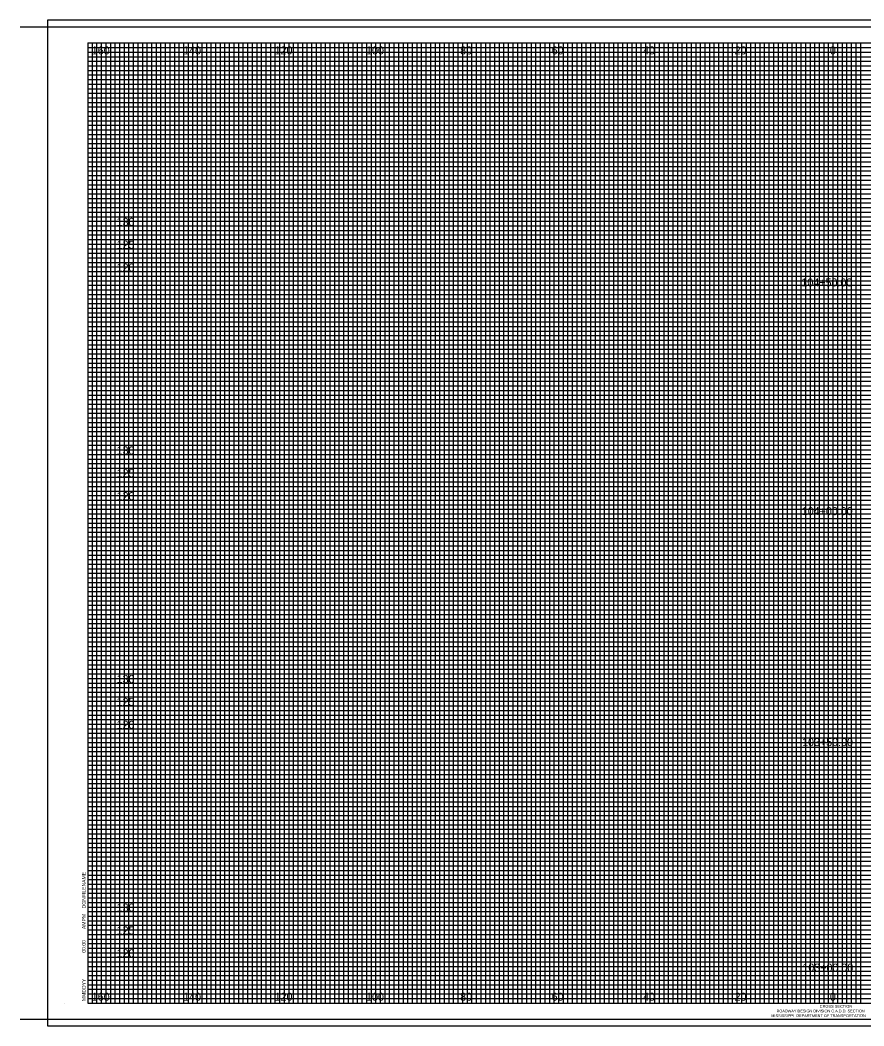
# Model space of a CAD drawing. Extents: x -3604 to 2303, y -13 to 9543.
# Drawn here: x -3604.5 to -3420, y 6914.1 to 7134.1 of the extents above; entities that cross this region are included whole.
import ezdxf

# ---------------------------------------------------------------- set-up
doc = ezdxf.new("R2010")
doc.units = 0
for name, color, linetype in [('SHEET_BORDER', 7, 'Continuous'), ('SHEET_BORDER_TX', 7, 'Continuous'), ('SHEET_DATE_DGN_TX', 7, 'Continuous'), ('SHEET_PLOTTING_SHAPE', 7, 'Continuous'), ('XS_SHEET_LABELS_ELEVATION', 7, 'Continuous'), ('XS_SHEET_LABELS_OFFSET', 7, 'Continuous'), ('XS_SHEET_LABELS_STATION', 7, 'Continuous'), ('XS_SHEET_MAJOR_GRIDS', 7, 'Continuous'), ('XS_SHEET_MEDIUM_GRIDS', 7, 'Continuous'), ('XS_SHEET_MINOR_GRIDS', 7, 'Continuous')]:
    doc.layers.add(name, color=color, linetype=linetype)

msp = doc.modelspace()

# ---------------------------------------------------------------- linework, layer by layer
at = {"layer": 'SHEET_BORDER'}
for p, q in [((-3604.48, 7132.59), (-3252.48, 7132.59)), ((-3589.68, 7129.09), (-3254.68, 7129.09)), ((-3589.68, 7129.09), (-3589.68, 6919.09)), ((-3445.68, 6919.09), (-3445.68, 7129.09)), ((-3594.68, 6919.09), (-3594.68, 6919.09)), ((-3589.68, 6919.09), (-3254.68, 6919.09)), ((-3604.48, 6915.59), (-3252.48, 6915.59))]:
    msp.add_line(p, q, dxfattribs=at)
at = {"layer": 'SHEET_PLOTTING_SHAPE'}
msp.add_lwpolyline([(-3598.48, 6914.09), (-3252.48, 6914.09), (-3252.48, 7134.09), (-3598.48, 7134.09)], close=True, dxfattribs=at)
at = {"layer": 'XS_SHEET_MAJOR_GRIDS'}
for p, q in [((-3584.68, 6919.09), (-3584.68, 7129.09)), ((-3574.68, 6919.09), (-3574.68, 7129.09)), ((-3564.68, 6919.09), (-3564.68, 7129.09)), ((-3554.68, 6919.09), (-3554.68, 7129.09)), ((-3544.68, 6919.09), (-3544.68, 7129.09)), ((-3534.68, 6919.09), (-3534.68, 7129.09)), ((-3524.68, 6919.09), (-3524.68, 7129.09)), ((-3514.68, 6919.09), (-3514.68, 7129.09)), ((-3504.68, 6919.09), (-3504.68, 7129.09)), ((-3494.68, 6919.09), (-3494.68, 7129.09)), ((-3484.68, 6919.09), (-3484.68, 7129.09)), ((-3474.68, 6919.09), (-3474.68, 7129.09)), ((-3464.68, 6919.09), (-3464.68, 7129.09)), ((-3454.68, 6919.09), (-3454.68, 7129.09)), ((-3444.68, 6919.09), (-3444.68, 7129.09)), ((-3434.68, 6919.09), (-3434.68, 7129.09)), ((-3424.68, 6919.09), (-3424.68, 7129.09)), ((-3589.68, 7119.09), (-3254.68, 7119.09)), ((-3589.68, 7109.09), (-3254.68, 7109.09)), ((-3589.68, 7099.09), (-3254.68, 7099.09)), ((-3589.68, 7089.09), (-3254.68, 7089.09)), ((-3589.68, 7079.09), (-3254.68, 7079.09)), ((-3589.68, 7069.09), (-3254.68, 7069.09)), ((-3589.68, 7059.09), (-3254.68, 7059.09)), ((-3589.68, 7049.09), (-3254.68, 7049.09)), ((-3589.68, 7039.09), (-3254.68, 7039.09)), ((-3589.68, 7029.09), (-3254.68, 7029.09)), ((-3589.68, 7019.09), (-3254.68, 7019.09)), ((-3589.68, 7009.09), (-3254.68, 7009.09)), ((-3589.68, 6999.09), (-3254.68, 6999.09)), ((-3589.68, 6989.09), (-3254.68, 6989.09)), ((-3589.68, 6979.09), (-3254.68, 6979.09)), ((-3589.68, 6969.09), (-3254.68, 6969.09)), ((-3589.68, 6959.09), (-3254.68, 6959.09)), ((-3589.68, 6949.09), (-3254.68, 6949.09)), ((-3589.68, 6939.09), (-3254.68, 6939.09)), ((-3589.68, 6929.09), (-3254.68, 6929.09))]:
    msp.add_line(p, q, dxfattribs=at)
at = {"layer": 'XS_SHEET_MEDIUM_GRIDS'}
for p, q in [((-3579.68, 6919.09), (-3579.68, 7129.09)), ((-3569.68, 6919.09), (-3569.68, 7129.09)), ((-3559.68, 6919.09), (-3559.68, 7129.09)), ((-3549.68, 6919.09), (-3549.68, 7129.09)), ((-3539.68, 6919.09), (-3539.68, 7129.09)), ((-3529.68, 6919.09), (-3529.68, 7129.09)), ((-3519.68, 6919.09), (-3519.68, 7129.09)), ((-3509.68, 6919.09), (-3509.68, 7129.09)), ((-3499.68, 6919.09), (-3499.68, 7129.09)), ((-3489.68, 6919.09), (-3489.68, 7129.09)), ((-3479.68, 6919.09), (-3479.68, 7129.09)), ((-3469.68, 6919.09), (-3469.68, 7129.09)), ((-3459.68, 6919.09), (-3459.68, 7129.09)), ((-3449.68, 6919.09), (-3449.68, 7129.09)), ((-3439.68, 6919.09), (-3439.68, 7129.09)), ((-3429.68, 6919.09), (-3429.68, 7129.09)), ((-3589.68, 7124.09), (-3281.68, 7124.09)), ((-3589.68, 7114.09), (-3254.68, 7114.09)), ((-3589.68, 7104.09), (-3254.68, 7104.09)), ((-3589.68, 7094.09), (-3254.68, 7094.09)), ((-3589.68, 7084.09), (-3254.68, 7084.09)), ((-3589.68, 7074.09), (-3254.68, 7074.09)), ((-3589.68, 7064.09), (-3254.68, 7064.09)), ((-3589.68, 7054.09), (-3254.68, 7054.09)), ((-3589.68, 7044.09), (-3254.68, 7044.09)), ((-3589.68, 7034.09), (-3254.68, 7034.09)), ((-3589.68, 7024.09), (-3254.68, 7024.09)), ((-3589.68, 7014.09), (-3254.68, 7014.09)), ((-3589.68, 7004.09), (-3254.68, 7004.09)), ((-3589.68, 6994.09), (-3254.68, 6994.09)), ((-3589.68, 6984.09), (-3254.68, 6984.09)), ((-3589.68, 6974.09), (-3254.68, 6974.09)), ((-3589.68, 6964.09), (-3254.68, 6964.09)), ((-3589.68, 6954.09), (-3254.68, 6954.09)), ((-3589.68, 6944.09), (-3254.68, 6944.09)), ((-3589.68, 6934.09), (-3254.68, 6934.09)), ((-3589.68, 6924.09), (-3264.68, 6924.09))]:
    msp.add_line(p, q, dxfattribs=at)
at = {"layer": 'XS_SHEET_MINOR_GRIDS'}
for p, q in [((-3589.68, 7128.09), (-3281.68, 7128.09)), ((-3588.68, 6919.09), (-3588.68, 7129.09)), ((-3587.68, 6919.09), (-3587.68, 7129.09)), ((-3586.68, 6919.09), (-3586.68, 7129.09)), ((-3585.68, 6919.09), (-3585.68, 7129.09)), ((-3583.68, 6919.09), (-3583.68, 7129.09)), ((-3582.68, 6919.09), (-3582.68, 7129.09)), ((-3581.68, 6919.09), (-3581.68, 7129.09)), ((-3580.68, 6919.09), (-3580.68, 7129.09)), ((-3578.68, 6919.09), (-3578.68, 7129.09)), ((-3577.68, 6919.09), (-3577.68, 7129.09)), ((-3576.68, 6919.09), (-3576.68, 7129.09)), ((-3575.68, 6919.09), (-3575.68, 7129.09)), ((-3573.68, 6919.09), (-3573.68, 7129.09)), ((-3572.68, 6919.09), (-3572.68, 7129.09)), ((-3571.68, 6919.09), (-3571.68, 7129.09)), ((-3570.68, 6919.09), (-3570.68, 7129.09)), ((-3568.68, 6919.09), (-3568.68, 7129.09)), ((-3567.68, 6919.09), (-3567.68, 7129.09)), ((-3566.68, 6919.09), (-3566.68, 7129.09)), ((-3565.68, 6919.09), (-3565.68, 7129.09)), ((-3563.68, 6919.09), (-3563.68, 7129.09)), ((-3562.68, 6919.09), (-3562.68, 7129.09)), ((-3561.68, 6919.09), (-3561.68, 7129.09)), ((-3560.68, 6919.09), (-3560.68, 7129.09)), ((-3558.68, 6919.09), (-3558.68, 7129.09)), ((-3557.68, 6919.09), (-3557.68, 7129.09)), ((-3556.68, 6919.09), (-3556.68, 7129.09)), ((-3555.68, 6919.09), (-3555.68, 7129.09)), ((-3553.68, 6919.09), (-3553.68, 7129.09)), ((-3552.68, 6919.09), (-3552.68, 7129.09)), ((-3551.68, 6919.09), (-3551.68, 7129.09)), ((-3550.68, 6919.09), (-3550.68, 7129.09)), ((-3548.68, 6919.09), (-3548.68, 7129.09)), ((-3547.68, 6919.09), (-3547.68, 7129.09)), ((-3546.68, 6919.09), (-3546.68, 7129.09)), ((-3545.68, 6919.09), (-3545.68, 7129.09)), ((-3543.68, 6919.09), (-3543.68, 7129.09)), ((-3542.68, 6919.09), (-3542.68, 7129.09)), ((-3541.68, 6919.09), (-3541.68, 7129.09)), ((-3540.68, 6919.09), (-3540.68, 7129.09)), ((-3538.68, 6919.09), (-3538.68, 7129.09)), ((-3537.68, 6919.09), (-3537.68, 7129.09)), ((-3536.68, 6919.09), (-3536.68, 7129.09)), ((-3535.68, 6919.09), (-3535.68, 7129.09)), ((-3533.68, 6919.09), (-3533.68, 7129.09)), ((-3532.68, 6919.09), (-3532.68, 7129.09)), ((-3531.68, 6919.09), (-3531.68, 7129.09)), ((-3530.68, 6919.09), (-3530.68, 7129.09)), ((-3528.68, 6919.09), (-3528.68, 7129.09)), ((-3527.68, 6919.09), (-3527.68, 7129.09)), ((-3526.68, 6919.09), (-3526.68, 7129.09)), ((-3525.68, 6919.09), (-3525.68, 7129.09)), ((-3523.68, 6919.09), (-3523.68, 7129.09)), ((-3522.68, 6919.09), (-3522.68, 7129.09)), ((-3521.68, 6919.09), (-3521.68, 7129.09)), ((-3520.68, 6919.09), (-3520.68, 7129.09)), ((-3518.68, 6919.09), (-3518.68, 7129.09)), ((-3517.68, 6919.09), (-3517.68, 7129.09)), ((-3516.68, 6919.09), (-3516.68, 7129.09)), ((-3515.68, 6919.09), (-3515.68, 7129.09)), ((-3513.68, 6919.09), (-3513.68, 7129.09)), ((-3512.68, 6919.09), (-3512.68, 7129.09)), ((-3511.68, 6919.09), (-3511.68, 7129.09)), ((-3510.68, 6919.09), (-3510.68, 7129.09)), ((-3508.68, 6919.09), (-3508.68, 7129.09)), ((-3507.68, 6919.09), (-3507.68, 7129.09)), ((-3506.68, 6919.09), (-3506.68, 7129.09)), ((-3505.68, 6919.09), (-3505.68, 7129.09)), ((-3503.68, 6919.09), (-3503.68, 7129.09)), ((-3502.68, 6919.09), (-3502.68, 7129.09)), ((-3501.68, 6919.09), (-3501.68, 7129.09)), ((-3500.68, 6919.09), (-3500.68, 7129.09)), ((-3498.68, 6919.09), (-3498.68, 7129.09)), ((-3497.68, 6919.09), (-3497.68, 7129.09)), ((-3496.68, 6919.09), (-3496.68, 7129.09)), ((-3495.68, 6919.09), (-3495.68, 7129.09)), ((-3493.68, 6919.09), (-3493.68, 7129.09)), ((-3492.68, 6919.09), (-3492.68, 7129.09)), ((-3491.68, 6919.09), (-3491.68, 7129.09)), ((-3490.68, 6919.09), (-3490.68, 7129.09)), ((-3488.68, 6919.09), (-3488.68, 7129.09)), ((-3487.68, 6919.09), (-3487.68, 7129.09)), ((-3486.68, 6919.09), (-3486.68, 7129.09)), ((-3485.68, 6919.09), (-3485.68, 7129.09)), ((-3483.68, 6919.09), (-3483.68, 7129.09)), ((-3482.68, 6919.09), (-3482.68, 7129.09)), ((-3481.68, 6919.09), (-3481.68, 7129.09)), ((-3480.68, 6919.09), (-3480.68, 7129.09)), ((-3478.68, 6919.09), (-3478.68, 7129.09)), ((-3477.68, 6919.09), (-3477.68, 7129.09)), ((-3476.68, 6919.09), (-3476.68, 7129.09)), ((-3475.68, 6919.09), (-3475.68, 7129.09)), ((-3473.68, 6919.09), (-3473.68, 7129.09)), ((-3472.68, 6919.09), (-3472.68, 7129.09)), ((-3471.68, 6919.09), (-3471.68, 7129.09)), ((-3470.68, 6919.09), (-3470.68, 7129.09)), ((-3468.68, 6919.09), (-3468.68, 7129.09)), ((-3467.68, 6919.09), (-3467.68, 7129.09)), ((-3466.68, 6919.09), (-3466.68, 7129.09)), ((-3465.68, 6919.09), (-3465.68, 7129.09)), ((-3463.68, 6919.09), (-3463.68, 7129.09)), ((-3462.68, 6919.09), (-3462.68, 7129.09)), ((-3461.68, 6919.09), (-3461.68, 7129.09)), ((-3460.68, 6919.09), (-3460.68, 7129.09)), ((-3458.68, 6919.09), (-3458.68, 7129.09)), ((-3457.68, 6919.09), (-3457.68, 7129.09)), ((-3456.68, 6919.09), (-3456.68, 7129.09)), ((-3455.68, 6919.09), (-3455.68, 7129.09)), ((-3453.68, 6919.09), (-3453.68, 7129.09)), ((-3452.68, 6919.09), (-3452.68, 7129.09)), ((-3451.68, 6919.09), (-3451.68, 7129.09)), ((-3450.68, 6919.09), (-3450.68, 7129.09)), ((-3448.68, 6919.09), (-3448.68, 7129.09)), ((-3447.68, 6919.09), (-3447.68, 7129.09)), ((-3446.68, 6919.09), (-3446.68, 7129.09)), ((-3443.68, 6919.09), (-3443.68, 7129.09)), ((-3442.68, 6919.09), (-3442.68, 7129.09)), ((-3441.68, 6919.09), (-3441.68, 7129.09)), ((-3440.68, 6919.09), (-3440.68, 7129.09)), ((-3438.68, 6919.09), (-3438.68, 7129.09)), ((-3437.68, 6919.09), (-3437.68, 7129.09)), ((-3436.68, 6919.09), (-3436.68, 7129.09)), ((-3435.68, 6919.09), (-3435.68, 7129.09)), ((-3433.68, 6919.09), (-3433.68, 7129.09)), ((-3432.68, 6919.09), (-3432.68, 7129.09)), ((-3431.68, 6919.09), (-3431.68, 7129.09)), ((-3430.68, 6919.09), (-3430.68, 7129.09)), ((-3428.68, 6919.09), (-3428.68, 7129.09)), ((-3427.68, 6919.09), (-3427.68, 7129.09)), ((-3426.68, 6919.09), (-3426.68, 7129.09)), ((-3425.68, 6919.09), (-3425.68, 7129.09)), ((-3423.68, 6919.09), (-3423.68, 7129.09)), ((-3422.68, 6919.09), (-3422.68, 7129.09)), ((-3421.68, 6919.09), (-3421.68, 7129.09)), ((-3420.68, 6919.09), (-3420.68, 7129.09)), ((-3589.68, 7127.09), (-3281.68, 7127.09)), ((-3589.68, 7126.09), (-3281.68, 7126.09)), ((-3589.68, 7125.09), (-3281.68, 7125.09)), ((-3589.68, 7123.09), (-3281.68, 7123.09)), ((-3589.68, 7122.09), (-3281.68, 7122.09)), ((-3589.68, 7121.09), (-3281.68, 7121.09)), ((-3589.68, 7120.09), (-3254.68, 7120.09)), ((-3589.68, 7118.09), (-3254.68, 7118.09)), ((-3589.68, 7117.09), (-3254.68, 7117.09)), ((-3589.68, 7116.09), (-3254.68, 7116.09)), ((-3589.68, 7115.09), (-3254.68, 7115.09)), ((-3589.68, 7113.09), (-3254.68, 7113.09)), ((-3589.68, 7112.09), (-3254.68, 7112.09)), ((-3589.68, 7111.09), (-3254.68, 7111.09)), ((-3589.68, 7110.09), (-3254.68, 7110.09)), ((-3589.68, 7108.09), (-3254.68, 7108.09)), ((-3589.68, 7107.09), (-3254.68, 7107.09)), ((-3589.68, 7106.09), (-3254.68, 7106.09)), ((-3589.68, 7105.09), (-3254.68, 7105.09)), ((-3589.68, 7103.09), (-3254.68, 7103.09)), ((-3589.68, 7102.09), (-3254.68, 7102.09)), ((-3589.68, 7101.09), (-3254.68, 7101.09)), ((-3589.68, 7100.09), (-3254.68, 7100.09)), ((-3589.68, 7098.09), (-3254.68, 7098.09)), ((-3589.68, 7097.09), (-3254.68, 7097.09)), ((-3589.68, 7096.09), (-3254.68, 7096.09)), ((-3589.68, 7095.09), (-3254.68, 7095.09)), ((-3589.68, 7093.09), (-3254.68, 7093.09)), ((-3589.68, 7092.09), (-3254.68, 7092.09)), ((-3589.68, 7091.09), (-3254.68, 7091.09)), ((-3589.68, 7090.09), (-3254.68, 7090.09)), ((-3589.68, 7088.09), (-3254.68, 7088.09)), ((-3589.68, 7087.09), (-3254.68, 7087.09)), ((-3589.68, 7086.09), (-3254.68, 7086.09)), ((-3589.68, 7085.09), (-3254.68, 7085.09)), ((-3589.68, 7083.09), (-3254.68, 7083.09)), ((-3589.68, 7082.09), (-3254.68, 7082.09)), ((-3589.68, 7081.09), (-3254.68, 7081.09)), ((-3589.68, 7080.09), (-3254.68, 7080.09)), ((-3589.68, 7078.09), (-3254.68, 7078.09)), ((-3589.68, 7077.09), (-3254.68, 7077.09)), ((-3589.68, 7076.09), (-3254.68, 7076.09)), ((-3589.68, 7075.09), (-3254.68, 7075.09)), ((-3589.68, 7073.09), (-3254.68, 7073.09)), ((-3589.68, 7072.09), (-3254.68, 7072.09)), ((-3589.68, 7071.09), (-3254.68, 7071.09)), ((-3589.68, 7070.09), (-3254.68, 7070.09)), ((-3589.68, 7068.09), (-3254.68, 7068.09)), ((-3589.68, 7067.09), (-3254.68, 7067.09)), ((-3589.68, 7066.09), (-3254.68, 7066.09)), ((-3589.68, 7065.09), (-3254.68, 7065.09)), ((-3589.68, 7063.09), (-3254.68, 7063.09)), ((-3589.68, 7062.09), (-3254.68, 7062.09)), ((-3589.68, 7061.09), (-3254.68, 7061.09)), ((-3589.68, 7060.09), (-3254.68, 7060.09)), ((-3589.68, 7058.09), (-3254.68, 7058.09)), ((-3589.68, 7057.09), (-3254.68, 7057.09)), ((-3589.68, 7056.09), (-3254.68, 7056.09)), ((-3589.68, 7055.09), (-3254.68, 7055.09)), ((-3589.68, 7053.09), (-3254.68, 7053.09)), ((-3589.68, 7052.09), (-3254.68, 7052.09)), ((-3589.68, 7051.09), (-3254.68, 7051.09)), ((-3589.68, 7050.09), (-3254.68, 7050.09)), ((-3589.68, 7048.09), (-3254.68, 7048.09)), ((-3589.68, 7047.09), (-3254.68, 7047.09)), ((-3589.68, 7046.09), (-3254.68, 7046.09)), ((-3589.68, 7045.09), (-3254.68, 7045.09)), ((-3589.68, 7043.09), (-3254.68, 7043.09)), ((-3589.68, 7042.09), (-3254.68, 7042.09)), ((-3589.68, 7041.09), (-3254.68, 7041.09)), ((-3589.68, 7040.09), (-3254.68, 7040.09)), ((-3589.68, 7038.09), (-3254.68, 7038.09)), ((-3589.68, 7037.09), (-3254.68, 7037.09)), ((-3589.68, 7036.09), (-3254.68, 7036.09)), ((-3589.68, 7035.09), (-3254.68, 7035.09)), ((-3589.68, 7033.09), (-3254.68, 7033.09)), ((-3589.68, 7032.09), (-3254.68, 7032.09)), ((-3589.68, 7031.09), (-3254.68, 7031.09)), ((-3589.68, 7030.09), (-3254.68, 7030.09)), ((-3589.68, 7028.09), (-3254.68, 7028.09)), ((-3589.68, 7027.09), (-3254.68, 7027.09)), ((-3589.68, 7026.09), (-3254.68, 7026.09)), ((-3589.68, 7025.09), (-3254.68, 7025.09)), ((-3589.68, 7023.09), (-3254.68, 7023.09)), ((-3589.68, 7022.09), (-3254.68, 7022.09)), ((-3589.68, 7021.09), (-3254.68, 7021.09)), ((-3589.68, 7020.09), (-3254.68, 7020.09)), ((-3589.68, 7018.09), (-3254.68, 7018.09)), ((-3589.68, 7017.09), (-3254.68, 7017.09)), ((-3589.68, 7016.09), (-3254.68, 7016.09)), ((-3589.68, 7015.09), (-3254.68, 7015.09)), ((-3589.68, 7013.09), (-3254.68, 7013.09)), ((-3589.68, 7012.09), (-3254.68, 7012.09)), ((-3589.68, 7011.09), (-3254.68, 7011.09)), ((-3589.68, 7010.09), (-3254.68, 7010.09)), ((-3589.68, 7008.09), (-3254.68, 7008.09)), ((-3589.68, 7007.09), (-3254.68, 7007.09)), ((-3589.68, 7006.09), (-3254.68, 7006.09)), ((-3589.68, 7005.09), (-3254.68, 7005.09)), ((-3589.68, 7003.09), (-3254.68, 7003.09)), ((-3589.68, 7002.09), (-3254.68, 7002.09)), ((-3589.68, 7001.09), (-3254.68, 7001.09)), ((-3589.68, 7000.09), (-3254.68, 7000.09)), ((-3589.68, 6998.09), (-3254.68, 6998.09)), ((-3589.68, 6997.09), (-3254.68, 6997.09)), ((-3589.68, 6996.09), (-3254.68, 6996.09)), ((-3589.68, 6995.09), (-3254.68, 6995.09)), ((-3589.68, 6993.09), (-3254.68, 6993.09)), ((-3589.68, 6992.09), (-3254.68, 6992.09)), ((-3589.68, 6991.09), (-3254.68, 6991.09)), ((-3589.68, 6990.09), (-3254.68, 6990.09)), ((-3589.68, 6988.09), (-3254.68, 6988.09)), ((-3589.68, 6987.09), (-3254.68, 6987.09)), ((-3589.68, 6986.09), (-3254.68, 6986.09)), ((-3589.68, 6985.09), (-3254.68, 6985.09)), ((-3589.68, 6983.09), (-3254.68, 6983.09)), ((-3589.68, 6982.09), (-3254.68, 6982.09)), ((-3589.68, 6981.09), (-3254.68, 6981.09)), ((-3589.68, 6980.09), (-3254.68, 6980.09)), ((-3589.68, 6978.09), (-3254.68, 6978.09)), ((-3589.68, 6977.09), (-3254.68, 6977.09)), ((-3589.68, 6976.09), (-3254.68, 6976.09)), ((-3589.68, 6975.09), (-3254.68, 6975.09)), ((-3589.68, 6973.09), (-3254.68, 6973.09)), ((-3589.68, 6972.09), (-3254.68, 6972.09)), ((-3589.68, 6971.09), (-3254.68, 6971.09)), ((-3589.68, 6970.09), (-3254.68, 6970.09)), ((-3589.68, 6968.09), (-3254.68, 6968.09)), ((-3589.68, 6967.09), (-3254.68, 6967.09)), ((-3589.68, 6966.09), (-3254.68, 6966.09)), ((-3589.68, 6965.09), (-3254.68, 6965.09)), ((-3589.68, 6963.09), (-3254.68, 6963.09)), ((-3589.68, 6962.09), (-3254.68, 6962.09)), ((-3589.68, 6961.09), (-3254.68, 6961.09)), ((-3589.68, 6960.09), (-3254.68, 6960.09)), ((-3589.68, 6958.09), (-3254.68, 6958.09)), ((-3589.68, 6957.09), (-3254.68, 6957.09)), ((-3589.68, 6956.09), (-3254.68, 6956.09)), ((-3589.68, 6955.09), (-3254.68, 6955.09)), ((-3589.68, 6953.09), (-3254.68, 6953.09)), ((-3589.68, 6952.09), (-3254.68, 6952.09)), ((-3589.68, 6951.09), (-3254.68, 6951.09)), ((-3589.68, 6950.09), (-3254.68, 6950.09)), ((-3589.68, 6948.09), (-3254.68, 6948.09)), ((-3589.68, 6947.09), (-3254.68, 6947.09)), ((-3589.68, 6946.09), (-3254.68, 6946.09)), ((-3589.68, 6945.09), (-3254.68, 6945.09)), ((-3589.68, 6943.09), (-3254.68, 6943.09)), ((-3589.68, 6942.09), (-3254.68, 6942.09)), ((-3589.68, 6941.09), (-3254.68, 6941.09)), ((-3589.68, 6940.09), (-3254.68, 6940.09)), ((-3589.68, 6940.09), (-3254.68, 6940.09)), ((-3589.68, 6940.09), (-3254.68, 6940.09)), ((-3589.68, 6938.09), (-3254.68, 6938.09)), ((-3589.68, 6937.09), (-3254.68, 6937.09)), ((-3589.68, 6936.09), (-3254.68, 6936.09)), ((-3589.68, 6935.09), (-3254.68, 6935.09)), ((-3589.68, 6933.09), (-3254.68, 6933.09)), ((-3589.68, 6932.09), (-3254.68, 6932.09)), ((-3589.68, 6931.09), (-3254.68, 6931.09)), ((-3589.68, 6930.09), (-3254.68, 6930.09)), ((-3589.68, 6928.09), (-3264.68, 6928.09)), ((-3589.68, 6927.09), (-3264.68, 6927.09)), ((-3589.68, 6926.09), (-3264.68, 6926.09)), ((-3589.68, 6925.09), (-3264.68, 6925.09)), ((-3589.68, 6925.09), (-3264.68, 6925.09)), ((-3589.68, 6925.09), (-3264.68, 6925.09)), ((-3589.68, 6923.09), (-3264.68, 6923.09)), ((-3589.68, 6922.09), (-3264.68, 6922.09)), ((-3589.68, 6921.09), (-3264.68, 6921.09)), ((-3589.68, 6920.09), (-3264.68, 6920.09))]:
    msp.add_line(p, q, dxfattribs=at)

# ---------------------------------------------------------------- texts
at = {"layer": 'SHEET_BORDER_TX'}
for s, height, p in [('ROADWAY DESIGN DIVISION C.A.D.D. SECTION', 0.61, (-3439.08, 6917.04)), ('CROSS SECTION', 0.62, (-3429.64, 6918.06)), ('MISSISSIPPI  DEPARTMENT OF TRANSPORTATION', 0.61, (-3440.24, 6916.01))]:
    msp.add_text(s, height=height, dxfattribs=at).set_placement(p)
at = {"layer": 'SHEET_DATE_DGN_TX'}
for s, p in [('DGNFILENAME', (-3590.15, 6939.79)), ('AMPM', (-3590.15, 6935.27)), ('00:00', (-3590.15, 6930.09)), ('MMDDYY', (-3590.15, 6919.51))]:
    msp.add_text(s, height=0.8, rotation=90, dxfattribs=at).set_placement(p)
at = {"layer": 'XS_SHEET_LABELS_ELEVATION'}
for s, p in [('  130  ', (-3584.68, 7089.09)), ('  125  ', (-3584.68, 7084.09)), ('  120  ', (-3584.68, 7079.09)), ('  130  ', (-3584.68, 7039.09)), ('  125  ', (-3584.68, 7034.09)), ('  120  ', (-3584.68, 7029.09)), ('  130  ', (-3584.68, 6989.09)), ('  125  ', (-3584.68, 6984.09)), ('  120  ', (-3584.68, 6979.09)), ('  130  ', (-3584.68, 6939.09)), ('  125  ', (-3584.68, 6934.09)), ('  120  ', (-3584.68, 6929.09))]:
    msp.add_text(s, height=1.75, dxfattribs=at).set_placement(p)
at = {"layer": 'XS_SHEET_LABELS_OFFSET'}
for s, p in [('  160  ', (-3590.11, 7126.59)), ('  140  ', (-3570.13, 7126.59)), ('  120  ', (-3550.13, 7126.59)), ('  100  ', (-3530.13, 7126.59)), ('  80  ', (-3509.56, 7126.59)), ('  60  ', (-3489.55, 7126.59)), ('  40  ', (-3469.56, 7126.59)), ('  20  ', (-3449.56, 7126.59)), ('  0  ', (-3428.71, 7126.59)), ('  0  ', (-3428.71, 7126.59)), ('  160  ', (-3590.11, 6919.59)), ('  140  ', (-3570.13, 6919.59)), ('  120  ', (-3550.13, 6919.59)), ('  100  ', (-3530.13, 6919.59)), ('  80  ', (-3509.56, 6919.59)), ('  60  ', (-3489.55, 6919.59)), ('  40  ', (-3469.56, 6919.59)), ('  20  ', (-3449.56, 6919.59)), ('  0  ', (-3428.71, 6919.59)), ('  0  ', (-3428.71, 6919.59))]:
    msp.add_text(s, height=1.75, dxfattribs=at).set_placement(p)
at = {"layer": 'XS_SHEET_LABELS_STATION'}
for s, p in [('  104+50.00  ', (-3434.94, 7075.84)), ('  104+00.00  ', (-3434.86, 7025.81)), ('  103+50.00  ', (-3434.79, 6975.29)), ('  103+00.00  ', (-3434.73, 6925.96))]:
    msp.add_text(s, height=1.75, dxfattribs=at).set_placement(p)

doc.saveas('drawing.dxf')
